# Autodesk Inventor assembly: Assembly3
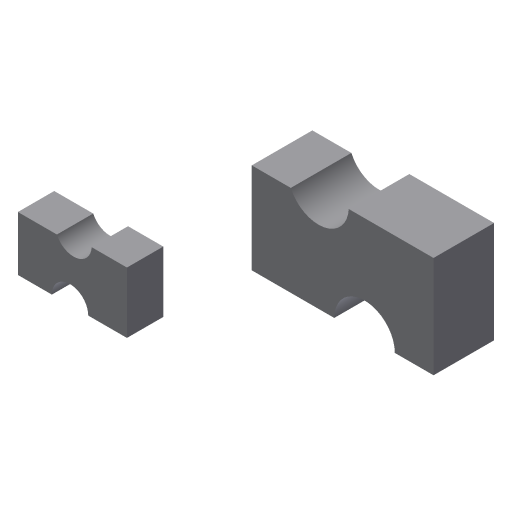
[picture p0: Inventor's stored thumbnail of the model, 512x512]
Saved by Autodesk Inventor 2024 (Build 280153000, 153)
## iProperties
Created: 2017-06
Part Number: Assembly3
Document SubType Name: Assembly
Designer: CADCIM 00
Author: CADCIM 00
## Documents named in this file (4)
- D:\PROJECTS\Project 2023\RESOURCES INVENTOR 2024\RESOURCES INVENTOR 2024\Inventor_2024_tut\Inventor_2024_tut\c18_Inv_2024_tut\c18_Inv_tut_2024\c18_tut04_inv\Assembly3.iam
- D:\PROJECTS\Project 2023\RESOURCES INVENTOR 2024\RESOURCES INVENTOR 2024\Inventor_2024_tut\Inventor_2024_tut\c18_Inv_2024_tut\c18_Inv_tut_2024\c18_tut04_inv\c18_tut04_inv-01.ipt
- E:\_Deepak\Inventor\Autodesk Inventor_2017_Project\Resources\Inventor_2018_tut\c18_Inv_tut_2018\c18_tut04_inv\c18_tut04_inv.ipt
- D:\PROJECTS\Project 2023\RESOURCES INVENTOR 2024\RESOURCES INVENTOR 2024\Inventor_2024_tut\Inventor_2024_tut\c18_Inv_2024_tut\c18_Inv_tut_2024\c18_tut04_inv\c18_tut04_inv-011.ipt
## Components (2 placed, 2 different names)
1. c18_tut04_inv-01:1
2. c18_tut04_inv-011:2
